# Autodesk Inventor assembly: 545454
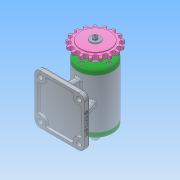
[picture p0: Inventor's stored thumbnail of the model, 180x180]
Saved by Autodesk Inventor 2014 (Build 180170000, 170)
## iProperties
Created: 2019-06
Part Number: 545454
Document SubType Name: Assembly
Designer: NET
Author: NET
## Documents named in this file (10)
- C:\Users\NET\Desktop\545454.iam
- C:\Users\NET\Desktop\787878.ipt
- C:\Users\NET\Desktop\축.ipt
- C:\Users\NET\Desktop\베어링 6203.ipt
- C:\Users\NET\Desktop\커버.ipt
- C:\Users\NET\Desktop\키 4x4x12.ipt
- C:\Users\NET\Desktop\스프로킷.ipt
- C:\Users\NET\Desktop\평와셔.ipt
- C:\Users\NET\Desktop\스프링와셔.ipt
- C:\Users\NET\Desktop\볼트 M4.ipt
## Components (1 placed, 1 different names)
1. 787878:1
